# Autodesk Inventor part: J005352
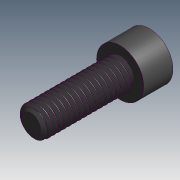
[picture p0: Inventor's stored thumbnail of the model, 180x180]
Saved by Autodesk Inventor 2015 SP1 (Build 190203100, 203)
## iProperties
Created: 2014-10
Part Number: J005352
Material: Generic
Document SubType Name: Modeling
Designer: arnoldj
Description: SCREW, SHC, SS, M4 x 12
Vendor: HHMI: JRC - JET
Appearance: Default
Project: P-201804
Translation Standard: STEP AP203
FileName: 92290A148.step
PreProcessor: SolidWorks 2013
PostProcessor: Build: 219, Release: 2012 SP2 - Date: Fri 04/27/2012
Sent Units: millimeter
Uncertainty: 1e-05
ALTERED ITEM PART NUMBER: 92290A148
ALTERED ITEM VENDOR: MCMASTER CARR
SPECIAL FINISH: NONE
SURFACE ROUGHNESS: N/A
DESIGN DEPARTMENT: HHMI: JRC - ID&F
ALTERED ITEM DESCRIPTION: MODIFIED M4 x 12 SHCS
LAB/DEPT: SVOBODA (LAB)
REQUESTING SCIENTIST: SOFRONIEW, NICK
Revision Number: -
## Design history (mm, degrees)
feature "Base1"
sketch "Sketch1"
  geometry: C1 r 3.175 at (0, 0); C2 r 3.731 at (0, 0); 1 further point
  constraints: 2 centre point, 2 coincident
  dimensions: "d0" = 6.35 diameter of C1
extrude "Extrusion1" cut sketch "Sketch1" stored distance "d1" = 10; taper "d2" = 0 deg
node "Chamfer1"
